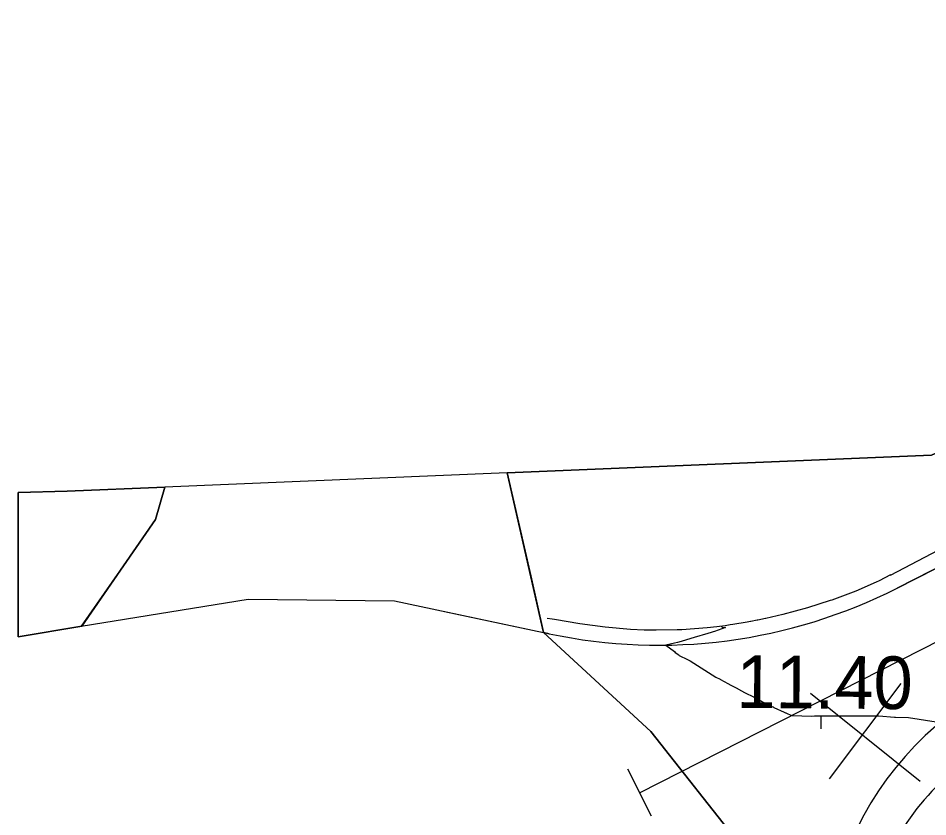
# Model space of a CAD drawing. Extents: x 554247.5 to 554326.1, y 6593477.6 to 6593537.1.
# Drawn here: x 554247.47 to 554264.74, y 6593498.07 to 6593513.23 of the extents above; entities that cross this region are included whole.
import ezdxf

# ---------------------------------------------------------------- set-up
doc = ezdxf.new("R2010")
doc.units = 0
for name, color, linetype in [('ASF', 7, 'Continuous'), ('FILL ASF KT', 7, 'Continuous'), ('FILL KILLUSTIK', 7, 'Continuous'), ('FILL ROHELINE', 7, 'Continuous'), ('LIKV', 7, 'Continuous'), ('NÕLV', 7, 'Continuous'), ('PK', 7, 'Continuous'), ('TELG', 7, 'Continuous'), ('VERT', 7, 'Continuous')]:
    doc.layers.add(name, color=color, linetype=linetype)

msp = doc.modelspace()

# ---------------------------------------------------------------- linework, layer by layer
at = {"layer": 'ASF'}
for points in [[(554264.161, 6593502.412), (554285.444, 6593513.231)], [(554255.568, 6593501.965), (554257.446, 6593501.567)], [(554263.226, 6593493.02), (554262.564, 6593494.685), (554261.213, 6593497.498), (554259.482, 6593499.687), (554257.446, 6593501.567), (554257.556, 6593501.544)]]:
    msp.add_lwpolyline(points, dxfattribs=at)
msp.add_lwpolyline([(554248.67, 6593501.688), (554251.838, 6593502.198), (554254.616, 6593502.167), (554257.446, 6593501.567), (554256.756, 6593504.598), (554250.26, 6593504.328), (554250.08, 6593503.71)], close=True, dxfattribs=at)
for centre, radius, start, end in [((554259.63, 6593511.326), 10, 258.0297, 296.945), ((554268.802, 6593495.236), 6, 116.9456, 201.6745)]:
    msp.add_arc(centre, radius, start, end, dxfattribs=at)
at = {"layer": 'FILL ASF KT'}
msp.add_line((554285.444, 6593513.231), (554264.161, 6593502.412), dxfattribs=at)
msp.add_lwpolyline([(554257.556, 6593501.544), (554257.446, 6593501.567), (554259.482, 6593499.687), (554261.213, 6593497.498), (554262.564, 6593494.685), (554263.226, 6593493.02)], dxfattribs=at)
for centre, radius, start, end in [((554259.63, 6593511.326), 10, 258.0297, 296.945), ((554268.802, 6593495.236), 6, 116.9456, 201.6745)]:
    msp.add_arc(centre, radius, start, end, dxfattribs=at)
at = {"layer": 'FILL KILLUSTIK'}
msp.add_lwpolyline([(554248.67, 6593501.688), (554251.838, 6593502.198), (554254.616, 6593502.167), (554257.446, 6593501.567), (554256.756, 6593504.598), (554250.26, 6593504.328), (554250.08, 6593503.71), (554248.67, 6593501.688)], dxfattribs=at)
at = {"layer": 'FILL ROHELINE'}
msp.add_line((554264.161, 6593502.412), (554271.79, 6593506.29), dxfattribs=at)
for points in [[(554257.556, 6593501.544), (554257.446, 6593501.567), (554257.204, 6593502.641), (554256.756, 6593504.598), (554264.814, 6593504.931), (554270.559, 6593507.573), (554270.797, 6593508.088), (554271.046, 6593507.591), (554271.293, 6593507.159), (554278.029, 6593510.583), (554278.724, 6593509.815), (554271.79, 6593506.29)], [(554271.79, 6593506.29), (554278.724, 6593509.815), (554278.029, 6593510.583), (554271.293, 6593507.159), (554271.046, 6593507.591), (554270.797, 6593508.088), (554270.559, 6593507.573), (554264.814, 6593504.931), (554256.756, 6593504.598), (554257.204, 6593502.641), (554257.446, 6593501.567), (554257.556, 6593501.544)], [(554271.79, 6593506.29), (554264.161, 6593502.412)], [(554248.401, 6593504.251), (554247.473, 6593504.224), (554247.473, 6593501.488), (554248.68, 6593501.69), (554250.08, 6593503.71), (554250.26, 6593504.328), (554248.401, 6593504.251)]]:
    msp.add_lwpolyline(points, dxfattribs=at)
msp.add_lwpolyline([(554250.26, 6593504.328), (554250.08, 6593503.71), (554248.68, 6593501.69), (554247.473, 6593501.488), (554247.473, 6593504.224), (554248.401, 6593504.251)], close=True, dxfattribs=at)
for centre, radius, start, end in [((554259.63, 6593511.326), 10, 258.0297, 296.945), ((554259.63, 6593511.326), 10, 258.0297, 296.945), ((554268.802, 6593495.236), 6, 116.9456, 201.6745), ((554268.802, 6593495.236), 6, 116.9456, 201.6745), ((554268.171, 6593495.373), 4.619, 110.7356, 154.1385), ((554268.171, 6593495.373), 4.619, 110.7356, 154.1385)]:
    msp.add_arc(centre, radius, start, end, dxfattribs=at)
at = {"layer": 'LIKV'}
for points in [[(554262.876, 6593498.789), (554264.234, 6593500.598)], [(554262.514, 6593500.417), (554264.596, 6593498.743)]]:
    msp.add_lwpolyline(points, dxfattribs=at)
at = {"layer": 'NÕLV'}
for points in [[(554264.036, 6593502.658), (554264.817, 6593503.064), (554265.698, 6593503.537), (554266.579, 6593504.011), (554267.46, 6593504.484), (554267.771, 6593504.645), (554267.906, 6593504.709), (554268.358, 6593504.924), (554268.829, 6593505.1), (554269.119, 6593505.634), (554269.462, 6593506.062), (554269.801, 6593506.498), (554270.141, 6593506.933), (554270.442, 6593507.317), (554270.482, 6593507.367), (554270.789, 6593508.098)], [(554264.035, 6593502.659), (554263.82, 6593502.551), (554263.764, 6593502.525), (554263.375, 6593502.355), (554262.92, 6593502.184), (554262.89, 6593502.174), (554262.458, 6593502.036), (554261.989, 6593501.909), (554261.669, 6593501.834), (554261.658, 6593501.832), (554261.517, 6593501.803), (554261.516, 6593501.802), (554261.5, 6593501.799), (554261.382, 6593501.776), (554261.379, 6593501.776), (554261.376, 6593501.775), (554261.316, 6593501.764), (554261.038, 6593501.717), (554260.989, 6593501.71), (554260.895, 6593501.696), (554260.736, 6593501.676), (554260.556, 6593501.655), (554260.072, 6593501.619), (554259.981, 6593501.615), (554259.586, 6593501.609), (554259.506, 6593501.61), (554259.361, 6593501.613), (554259.358, 6593501.613), (554259.355, 6593501.613), (554259.1, 6593501.625), (554258.616, 6593501.666), (554258.136, 6593501.734), (554257.656, 6593501.811), (554257.614, 6593501.819), (554257.517, 6593501.836)]]:
    msp.add_lwpolyline(points, dxfattribs=at)
at = {"layer": 'PK'}
msp.add_line((554259.498, 6593498.079), (554259.045, 6593498.97), dxfattribs=at)
at = {"layer": 'TELG'}
msp.add_lwpolyline([(554259.272, 6593498.524), (554286.011, 6593512.116)], dxfattribs=at)
at = {"layer": 'VERT'}
msp.add_line((554262.715, 6593499.735), (554262.717, 6593499.985), dxfattribs=at)
msp.add_lwpolyline([(554260.82, 6593501.686), (554260.825, 6593501.681), (554260.829, 6593501.677), (554260.83, 6593501.675), (554260.831, 6593501.674), (554260.832, 6593501.673), (554260.832, 6593501.673), (554260.832, 6593501.673), (554260.833, 6593501.673), (554260.833, 6593501.673), (554260.833, 6593501.672), (554260.836, 6593501.668), (554260.88, 6593501.665), (554260.898, 6593501.662), (554260.898, 6593501.66), (554260.899, 6593501.659), (554260.764, 6593501.612), (554260.744, 6593501.605), (554260.714, 6593501.595), (554260.566, 6593501.546), (554260.309, 6593501.471), (554260.081, 6593501.404), (554260.059, 6593501.398), (554259.989, 6593501.38), (554259.934, 6593501.367), (554259.769, 6593501.329), (554259.931, 6593501.204), (554259.932, 6593501.204), (554259.932, 6593501.204), (554259.947, 6593501.19), (554260.013, 6593501.14), (554260.025, 6593501.131), (554260.181, 6593501.053), (554260.231, 6593501.027), (554260.72, 6593500.721), (554260.799, 6593500.68), (554260.806, 6593500.677), (554260.943, 6593500.596), (554261.004, 6593500.565), (554261.04, 6593500.547), (554261.105, 6593500.515), (554261.207, 6593500.457), (554261.26, 6593500.428), (554261.445, 6593500.337), (554261.468, 6593500.324), (554261.536, 6593500.291), (554261.54, 6593500.29), (554261.543, 6593500.288), (554261.648, 6593500.226), (554261.784, 6593500.163), (554261.803, 6593500.154), (554261.805, 6593500.153), (554261.82, 6593500.144), (554261.82, 6593500.144), (554261.821, 6593500.143), (554262.016, 6593500.054), (554262.028, 6593500.047), (554262.043, 6593500.04), (554262.045, 6593500.039), (554262.045, 6593500.039), (554262.155, 6593499.99), (554262.165, 6593499.99), (554262.536, 6593499.979), (554262.589, 6593499.987), (554263.057, 6593499.983), (554263.143, 6593499.982), (554263.312, 6593499.986), (554263.369, 6593499.985), (554263.402, 6593499.984), (554263.81, 6593499.982), (554263.813, 6593499.982), (554264.111, 6593499.957), (554264.132, 6593499.957), (554264.379, 6593499.953), (554264.904, 6593499.87)], dxfattribs=at)

# ---------------------------------------------------------------- texts
msp.add_text('11.40', height=1, rotation=359.5435, dxfattribs=at).set_placement((554261.106, 6593500.137))

doc.saveas('drawing.dxf')
